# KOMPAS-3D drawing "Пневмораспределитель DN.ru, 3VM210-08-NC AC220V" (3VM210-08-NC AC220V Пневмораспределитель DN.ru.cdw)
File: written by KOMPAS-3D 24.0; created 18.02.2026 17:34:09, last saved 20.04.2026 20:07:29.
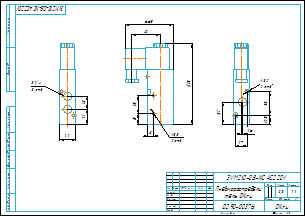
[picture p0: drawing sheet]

Document properties: Автор: R2D2; Форматы листов документа: A3; Полное имя файла: 3VM210-08-NC AC220V Пневмораспределитель DN.ru.m3d; Масса: 0.3; Наименование: Пневмораспределитель DN.ru; Количество листов документа: 1; Примечание: D290-00376

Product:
- Part/product: Пневмораспределитель DN.ru  | designation 3VM210-08-NC AC220V
    Масса: 0.3
    Раздел спецификации: Прочие изделия
    Примечание: D290-00376

Views: Вид 1, Спереди, Проекционный вид 2, Проекционный вид 3
Referenced files in E:\Работа\Зайцев\Аксессуары для пневмоприводов\Пневмораспределители DN.ru\3VM210-06-NC Пневмораспределитель DN.RU\AC24V\: 3VM210-06-NC AC24V Пневмораспределитель DN.ru.m3d
Referenced files in E:\Работа\Зайцев\Аксессуары для пневмоприводов\Пневмораспределители DN.ru\3VM210-08-NC Пневмораспределитель DN.RU\AC220V\: 3VM210-08-NC AC220V Пневмораспределитель DN.ru.m3d
Referenced files in E:\Работа\Зайцев\Для компаса\: чертеж DN.ru А3.cdt
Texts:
  чертеж DN.ru А3.cdt
  Пневмораспредели
  тель DN.ru
  Пневмораспределитель DN.ru
  3VM210-08-NC AC220V Пневмораспределитель DN.ru
Dimensions and other numbers on the sheet: 0; 3; 2; 4; 3 отв.; 21; 18; 22; 3VM210-08-NC AC220V; 66,5; 40; 111,5; 3,3; 2 отв.; 15; 25; 8; 9; 3,2; 33; 12,5; 17; 1,6; 31; 6; 1:1; 1; 0,3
